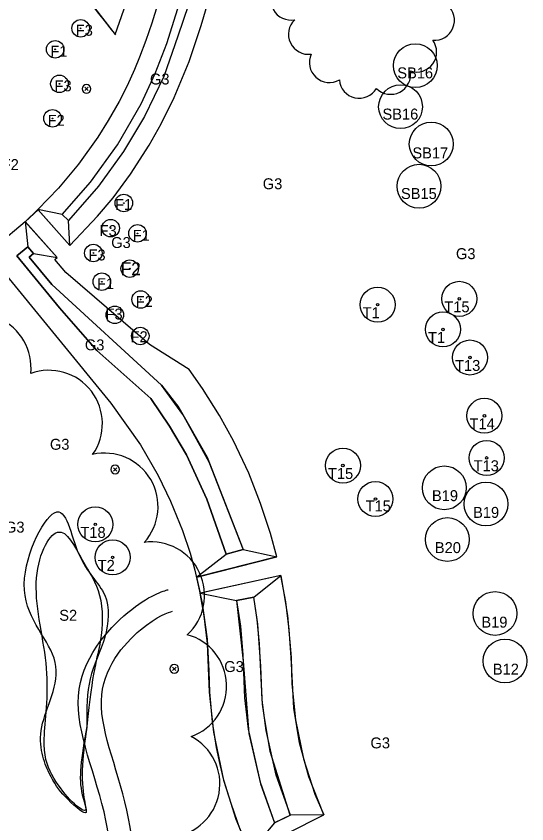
# Model space of a CAD drawing. Extents: x 0 to 512122, y 0 to 6212554.
# Drawn here: x 511698.8 to 511757.1, y 6211506.3 to 6211598.5 of the extents above; entities that cross this region are included whole.
import ezdxf

# ---------------------------------------------------------------- set-up
doc = ezdxf.new("R2010")
doc.units = 0
for name, color, linetype in [('_lights', 7, 'Continuous'), ('_LØ2', 7, 'Continuous'), ('_ny fruit trees', 7, 'Continuous'), ('_Paths', 7, 'Continuous'), ('_S2_skovjorbær', 7, 'Continuous'), ('Clouds', 7, 'Continuous'), ('L40 jord udlagt muld og grøft', 7, 'Continuous'), ('Skel', 7, 'Continuous'), ('TV_U_AFM_Symbl_Gul', 7, 'Continuous'), ('TV_U_LYS_Mastenummer', 7, 'Continuous')]:
    doc.layers.add(name, color=color, linetype=linetype)

# ---------------------------------------------------------------- blocks, each defined once
blk = doc.blocks.new('SOLITAIRE TREES')
at = {"layer": 'Skel'}
for radius in [2, 0.141]:
    blk.add_circle((0, 0), radius, dxfattribs=at)

msp = doc.modelspace()

# ---------------------------------------------------------------- linework, layer by layer
at = {"layer": '_lights'}
for p, q in [((511706.661, 6211590.395), (511707.055, 6211590.001)), ((511707.059, 6211590.399), (511706.664, 6211590.005)), ((511709.93, 6211546.947), (511710.324, 6211546.553)), ((511710.328, 6211546.951), (511709.933, 6211546.557)), ((511716.685, 6211524.194), (511717.079, 6211523.8)), ((511717.083, 6211524.198), (511716.689, 6211523.804))]:
    msp.add_line(p, q, dxfattribs=at)
for centre, start, end in [((511706.858, 6211590.198), 315.56363, 315), ((511706.858, 6211590.198), 315, 315.56363), ((511710.127, 6211546.75), 315.56363, 315), ((511710.127, 6211546.75), 315, 315.56363), ((511716.882, 6211523.997), 315.56363, 315), ((511716.882, 6211523.997), 315, 315.56363)]:
    msp.add_arc(centre, 0.5, start, end, dxfattribs=at)
at = {"layer": '_LØ2'}
msp.add_lwpolyline([(511711.121, 6211599.231), (511715.557, 6211615.262), (511713.457, 6211620.03), (511710.963, 6211624.728), (511708.398, 6211628.07), (511706.573, 6211631.603), (511706.496, 6211631.752), (511706.246, 6211631.811), (511705.782, 6211631.027), (511705.291, 6211628.924), (511704.763, 6211625.953), (511704.035, 6211622.995), (511702.625, 6211619.644), (511701.216, 6211616.293), (511699.914, 6211614.606), (511697.985, 6211612.99), (511704.249, 6211604.056), (511710.152, 6211596.395)], close=True, dxfattribs=at)
at = {"layer": '_ny fruit trees'}
for centre, radius in [((511706.195, 6211597.119), 1), ((511706.195, 6211597.119), 0.0426), ((511703.289, 6211594.72), 1), ((511703.289, 6211594.72), 0.0426), ((511703.77, 6211590.774), 1), ((511703.77, 6211590.774), 0.0426), ((511702.979, 6211586.835), 1), ((511702.979, 6211586.835), 0.0426), ((511711.129, 6211577.168), 1), ((511711.129, 6211577.168), 0.0426), ((511709.627, 6211574.296), 1), ((511709.627, 6211574.296), 0.0426), ((511712.691, 6211573.707), 1), ((511712.691, 6211573.707), 0.0426), ((511707.645, 6211571.466), 1), ((511707.645, 6211571.466), 0.0426), ((511711.799, 6211569.68), 1), ((511711.799, 6211569.68), 0.0426), ((511708.612, 6211568.187), 1), ((511708.612, 6211568.187), 0.0426), ((511713.041, 6211566.153), 1), ((511713.041, 6211566.153), 0.0426), ((511710.092, 6211564.402), 1), ((511710.092, 6211564.402), 0.0426), ((511712.999, 6211561.991), 1), ((511712.999, 6211561.991), 0.0426)]:
    msp.add_circle(centre, radius, dxfattribs=at)
at = {"layer": '_Paths'}
msp.add_arc((511888.3, 6211739.773), 228.678, 210.53527, 218.83127, dxfattribs=at)
for points in [[(511709.794, 6211493.646), (511709.91, 6211496.225), (511710.394, 6211506.9), (511703.249, 6211521.637), (511712.202, 6211531.873), (511715.701, 6211532.904), (511716.191, 6211533.023)], [(511712.291, 6211493.533), (511712.408, 6211496.112), (511712.92, 6211507.421), (511706.221, 6211521.237), (511713.557, 6211529.625), (511716.31, 6211530.475), (511716.669, 6211530.567)]]:
    msp.add_open_spline(points, degree=3, dxfattribs=at)
at = {"layer": '_S2_skovjorbær'}
for points in [[(511706.9, 6211517.437), (511706.892, 6211519.577), (511706.879, 6211522.919), (511709.268, 6211527.503), (511709.714, 6211532.722), (511705.511, 6211536.023), (511704.13, 6211545.757), (511697.258, 6211531.813), (511705.48, 6211524.913), (511700.578, 6211516.921), (511702.737, 6211511.52), (511704.109, 6211509.575), (511707.503, 6211506.503), (511706.171, 6211509.621), (511706.068, 6211512.581), (511706.587, 6211515.609), (511706.9, 6211517.437)], [(511706.9, 6211517.437), (511707.492, 6211523.66), (511708.75, 6211526.938), (511708.75, 6211532.814), (511706.419, 6211536.011), (511703.743, 6211541.801), (511699.992, 6211534.352), (511703.054, 6211523.695), (511701.621, 6211515.175), (511702.691, 6211511.885), (511705.03, 6211508.809), (511707.008, 6211507.37), (511706.639, 6211508.62), (511706.183, 6211512.117), (511706.9, 6211517.437), (511706.9, 6211517.437), (511706.9, 6211517.437)]]:
    msp.add_open_spline(points, degree=3, dxfattribs=at)
at = {"layer": 'Clouds'}
for centre, radius, start, end in [((511730.21, 6211600.334), 2.281, 135.97481, 280.97481), ((511746.596, 6211598.041), 2.281, 264.86251, 49.86251), ((511732.203, 6211596.43), 2.281, 133.09597, 278.09597), ((511744.56, 6211594.412), 2.281, 251.54538, 36.54538), ((511734.591, 6211593.208), 2.281, 154.99744, 299.99744), ((511741.59, 6211591.862), 2.28, 224.75506, 9.75506), ((511738.005, 6211591.413), 2.281, 184.52803, 329.52803), ((511694.432, 6211558.386), 6.099, 353.63977, 138.63977), ((511702.572, 6211551.974), 6.102, 324.91784, 109.91784), ((511708.927, 6211542.521), 6.1, 317.90586, 102.90586), ((511714.25, 6211532.384), 6.101, 312.5012, 97.5012), ((511716.765, 6211522.002), 6.1, 289.73226, 74.73226), ((511715.992, 6211510.857), 6.101, 277.3369, 62.3369)]:
    msp.add_arc(centre, radius, start, end, dxfattribs=at)
at = {"layer": 'L40 jord udlagt muld og grøft'}
for points in [[(511704.816, 6211575.161), (511704.095, 6211575.854), (511707.325, 6211579.538), (511710.411, 6211583.817), (511713.1, 6211588.498), (511714.705, 6211591.954), (511716.026, 6211595.388), (511717.675, 6211600.653), (511719.44, 6211607.105), (511719.454, 6211607.157), (511720.42, 6211606.898), (511718.52, 6211599.808), (511717.276, 6211596.237), (511715.672, 6211591.632), (511713.465, 6211587.061), (511711.085, 6211583.038), (511708.244, 6211579.086)], [(511704.957, 6211572.324), (511704.816, 6211575.161), (511704.095, 6211575.854), (511701.321, 6211576.416)], [(511699.863, 6211575.045), (511700.155, 6211572.157), (511700.819, 6211571.41), (511703.495, 6211570.958)], [(511718.204, 6211552.421), (511717.851, 6211553.035), (511715.427, 6211556.363), (511702.905, 6211567.862), (511700.329, 6211571.001), (511700.819, 6211571.41), (511700.155, 6211572.157), (511698.923, 6211571.141), (511703.772, 6211565.212), (511708.023, 6211560.353), (511714.189, 6211554.841), (511716.34, 6211551.696), (511718.265, 6211548.408), (511720.589, 6211543.361), (511722.822, 6211537.074), (511724.743, 6211537.632), (511724.743, 6211537.632), (511724.741, 6211537.635), (511720.88, 6211547.575)], [(511719.435, 6211534.452), (511722.822, 6211537.074), (511724.743, 6211537.632), (511728.578, 6211536.793)], [(511724.001, 6211531.806), (511725.968, 6211532.17), (511729.061, 6211534.649), (511719.839, 6211532.638)], [(511728.345, 6211506.392), (511730.134, 6211507.292), (511727.833, 6211514.541), (511727.153, 6211518.666), (511726.974, 6211519.96), (511726.825, 6211522.133), (511726.63, 6211526.831), (511726.344, 6211529.638), (511725.969, 6211532.17), (511724.001, 6211531.806), (511724.428, 6211528.848), (511724.708, 6211525.594), (511724.906, 6211520.68), (511725.327, 6211517.117), (511726.691, 6211511.047)], [(511725.515, 6211503.063), (511733.949, 6211507.31), (511730.135, 6211507.293), (511728.345, 6211506.392)]]:
    msp.add_lwpolyline(points, close=True, dxfattribs=at)
for points in [[(511725.59, 6211503.101), (511733.949, 6211507.31), (511732.241, 6211511.676), (511731.196, 6211515.541), (511730.542, 6211519.492), (511730.226, 6211525.301), (511730, 6211528.469), (511729.603, 6211531.621), (511729.061, 6211534.645), (511719.87, 6211532.645), (511719.475, 6211534.462), (511728.578, 6211536.793), (511727.862, 6211539.455), (511726.746, 6211542.873), (511725.379, 6211546.328), (511723.637, 6211550.012), (511722.047, 6211552.9), (511720.101, 6211555.995), (511718.583, 6211558.15), (511714.069, 6211561.036), (511704.496, 6211569.226), (511703.256, 6211570.742), (511703.495, 6211570.958), (511699.87, 6211575.038), (511701.326, 6211576.41), (511704.95, 6211572.331), (511708.125, 6211575.659), (511709.892, 6211577.782), (511711.896, 6211580.476), (511714.021, 6211583.766), (511715.401, 6211586.2), (511716.889, 6211589.209), (511718.584, 6211593.332), (511719.958, 6211597.433), (511721.235, 6211601.868)], [(511714.965, 6211599.808), (511714.305, 6211597.689), (511713.641, 6211595.742), (511712.913, 6211593.815), (511712.33, 6211592.408), (511711.489, 6211590.571), (511710.575, 6211588.77), (511709.336, 6211586.582), (511708.154, 6211584.697), (511705.941, 6211581.604), (511703.655, 6211578.856), (511701.322, 6211576.415), (511699.849, 6211575.03), (511696.652, 6211572.362)], [(511700.155, 6211572.157), (511700.819, 6211571.41), (511700.329, 6211571.001), (511702.905, 6211567.862), (511715.427, 6211556.363), (511717.394, 6211553.83), (511720.654, 6211548.158), (511724.743, 6211537.632), (511722.822, 6211537.074), (511720.589, 6211543.361), (511718.265, 6211548.408), (511716.34, 6211551.696), (511714.189, 6211554.841), (511708.023, 6211560.353), (511703.772, 6211565.212), (511698.923, 6211571.141), (511700.155, 6211572.157)], [(511696.979, 6211569.786), (511709.631, 6211554.305), (511713.041, 6211549.546), (511715.061, 6211546.048), (511716.471, 6211543.141), (511717.832, 6211539.77), (511718.692, 6211537.183), (511719.238, 6211535.238), (511720.059, 6211531.49), (511720.623, 6211527.389), (511720.84, 6211523.762), (511720.918, 6211521.336), (511721.227, 6211517.926), (511721.679, 6211515), (511722.077, 6211513.076), (511722.517, 6211511.293), (511723.396, 6211508.536), (511724.373, 6211505.698)], [(511725.968, 6211532.17), (511729.061, 6211534.649), (511729.816, 6211530.077), (511730.226, 6211525.301), (511730.322, 6211522.287), (511730.719, 6211518.15), (511731.642, 6211513.705), (511732.943, 6211509.699), (511733.949, 6211507.31), (511730.135, 6211507.293), (511728.53, 6211511.844), (511727.368, 6211516.937), (511726.937, 6211520.394), (511726.766, 6211524.24), (511726.415, 6211529.079), (511725.968, 6211532.17)], [(511719.839, 6211532.638), (511724.001, 6211531.806), (511724.74, 6211524.875), (511725.395, 6211516.61), (511726.738, 6211510.846), (511728.345, 6211506.392), (511725.515, 6211503.063), (511723.956, 6211506.779), (511722.525, 6211511.267), (511721.385, 6211516.76), (511720.918, 6211521.335), (511720.667, 6211526.885), (511720.297, 6211530.045), (511719.839, 6211532.638)]]:
    msp.add_lwpolyline(points, dxfattribs=at)
at = {"layer": 'TV_U_LYS_Mastenummer'}
for centre in [(511744.411, 6211592.864), (511744.411, 6211592.864), (511742.718, 6211588.162), (511742.718, 6211588.162), (511746.221, 6211583.904), (511746.221, 6211583.904), (511744.828, 6211579.091), (511744.828, 6211579.091), (511747.714, 6211544.655), (511747.714, 6211544.655), (511752.47, 6211542.808), (511752.47, 6211542.808), (511748.064, 6211538.755), (511748.064, 6211538.755), (511753.509, 6211530.311), (511753.509, 6211530.311), (511754.638, 6211524.889), (511754.638, 6211524.889)]:
    msp.add_circle(centre, 2.5, dxfattribs=at)

# ---------------------------------------------------------------- block references
at = {"layer": 'Skel'}
for p in [(511740.097, 6211565.561), (511749.421, 6211566.233), (511747.558, 6211562.736), (511750.646, 6211559.536), (511752.297, 6211552.879), (511752.549, 6211548.074), (511736.133, 6211547.202), (511739.855, 6211543.375), (511707.866, 6211540.478), (511709.843, 6211536.708)]:
    msp.add_blockref('SOLITAIRE TREES', p, dxfattribs=at)

# ---------------------------------------------------------------- texts
at = {"layer": 'TV_U_AFM_Symbl_Gul'}
for s, height, p in [('F3', 1.25, (511705.64, 6211596.27)), ('F1', 1.25, (511702.735, 6211593.872)), ('SB16', 1.25, (511742.346, 6211591.405)), ('G3', 1.25, (511714.109, 6211590.704)), ('F3', 1.25, (511703.216, 6211589.926)), ('SB16', 1.25, (511740.653, 6211586.702)), ('F2', 1.25, (511702.424, 6211585.987)), ('SB17', 1.25, (511744.07, 6211582.271)), ('F2', 1.25, (511697.182, 6211580.935)), ('G3', 1.25, (511726.989, 6211578.746)), ('SB15', 1.25, (511742.763, 6211577.632)), ('F1', 1.25, (511710.126, 6211576.379)), ('F3', 1.25, (511708.354, 6211573.399)), ('F1', 1.25, (511712.136, 6211572.859)), ('G3', 1.25, (511709.683, 6211572.036)), ('G3', 1.25, (511749.045, 6211570.763)), ('F3', 1.25, (511707.09, 6211570.617)), ('F2', 1.4722, (511710.764, 6211568.93)), ('F1', 1.25, (511708.057, 6211567.338)), ('F2', 1.25, (511712.486, 6211565.305)), ('T15', 1.25, (511747.719, 6211564.698)), ('F3', 1.25, (511709.032, 6211563.872)), ('T1', 1.25, (511738.394, 6211564.026)), ('F2', 1.25, (511711.898, 6211561.281)), ('T1', 1.25, (511745.855, 6211561.202)), ('G3', 1.25, (511706.678, 6211560.353)), ('T13', 1.25, (511748.943, 6211558.002)), ('T14', 1.25, (511750.594, 6211551.344)), ('G3', 1.25, (511702.687, 6211549.001)), ('T13', 1.25, (511751.063, 6211546.551)), ('T15', 1.25, (511734.431, 6211545.667)), ('B19', 1.25, (511746.305, 6211543.138)), ('T15', 1.25, (511738.726, 6211541.961)), ('B19', 1.25, (511750.999, 6211541.224)), ('G3', 1.25, (511697.556, 6211539.545)), ('T18', 1.25, (511706.164, 6211538.943)), ('B20', 1.25, (511746.636, 6211537.206)), ('T2', 1.25, (511708.14, 6211535.173)), ('S2', 1.25, (511703.751, 6211529.476)), ('B19', 1.25, (511751.947, 6211528.696)), ('G3', 1.25, (511722.588, 6211523.625)), ('B12', 1.25, (511753.257, 6211523.328)), ('G3', 1.25, (511739.284, 6211514.909))]:
    msp.add_text(s, height=height, dxfattribs=at).set_placement(p)

doc.saveas('drawing.dxf')
